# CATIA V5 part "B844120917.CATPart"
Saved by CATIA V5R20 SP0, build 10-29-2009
Part number: B844120917
Revision: 2
Definition: design
Nomenclature: B844120917
Source: made
Description: NOT SPECIFIED
Bounding box of the stored display mesh (mm): x -12.5 to 12.5, y -12.5 to 12.5, z -9 to 17
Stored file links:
  C:\Users\Utente\Desktop\3D files B844\B844120917.CATPart
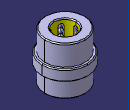
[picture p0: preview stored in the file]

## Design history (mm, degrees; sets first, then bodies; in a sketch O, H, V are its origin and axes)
Body1 "MANIFOLD_SOLID_BREP #38" (main body)
  Solid1: solid without history
Body2 "MANIFOLD_SOLID_BREP #76"
  Solid2: solid without history
Body3 "MANIFOLD_SOLID_BREP #114"
  Solid3: solid without history
Body4 "MANIFOLD_SOLID_BREP #152"
  Solid4: solid without history
Body5 "MANIFOLD_SOLID_BREP #190"
  Solid5: solid without history
Body6 "MANIFOLD_SOLID_BREP #228"
  Solid6: solid without history
Body7 "MANIFOLD_SOLID_BREP #266"
  Solid7: solid without history
Body8 "MANIFOLD_SOLID_BREP #1936"
  Solid8: solid without history
Body9 "MANIFOLD_SOLID_BREP #1974"
  Solid9: solid without history
Body10 "MANIFOLD_SOLID_BREP #2012"
  Solid10: solid without history
Body11 "MANIFOLD_SOLID_BREP #2050"
  Solid11: solid without history
Body12 "MANIFOLD_SOLID_BREP #2088"
  Solid12: solid without history
Body13 "MANIFOLD_SOLID_BREP #2126"
  Solid13: solid without history
Body14 "MANIFOLD_SOLID_BREP #2164"
  Solid14: solid without history
Body15 "MANIFOLD_SOLID_BREP #2202"
  Solid15: solid without history
Body16 "MANIFOLD_SOLID_BREP #2240"
  Solid16: solid without history
Body17 "MANIFOLD_SOLID_BREP #2278"
  Solid17: solid without history
Body18 "MANIFOLD_SOLID_BREP #2316"
  Solid18: solid without history
Body19 "MANIFOLD_SOLID_BREP #2354"
  Solid19: solid without history
Body20 "MANIFOLD_SOLID_BREP #2392"
  Solid20: solid without history
Body21 "MANIFOLD_SOLID_BREP #2430"
  Solid21: solid without history
Body22 "MANIFOLD_SOLID_BREP #2468"
  Solid22: solid without history
Body23 "MANIFOLD_SOLID_BREP #2506"
  Solid23: solid without history
Body24 "MANIFOLD_SOLID_BREP #2544"
  Solid24: solid without history
Body25 "MANIFOLD_SOLID_BREP #2582"
  Solid25: solid without history
Body26 "MANIFOLD_SOLID_BREP #2620"
  Solid26: solid without history
Body27 "MANIFOLD_SOLID_BREP #2658"
  Solid27: solid without history
Body28 "MANIFOLD_SOLID_BREP #2696"
  Solid28: solid without history
Body29 "MANIFOLD_SOLID_BREP #2734"
  Solid29: solid without history
Body30 "MANIFOLD_SOLID_BREP #2772"
  Solid30: solid without history
Body31 "MANIFOLD_SOLID_BREP #2810"
  Solid31: solid without history
Body32 "MANIFOLD_SOLID_BREP #2848"
  Solid32: solid without history
Body33 "MANIFOLD_SOLID_BREP #2886"
  Solid33: solid without history
Body34 "MANIFOLD_SOLID_BREP #2924"
  Solid34: solid without history
Body35 "MANIFOLD_SOLID_BREP #2962"
  Solid35: solid without history
Body36 "MANIFOLD_SOLID_BREP #3000"
  Solid36: solid without history
Body37 "MANIFOLD_SOLID_BREP #3038"
  Solid37: solid without history
Body38 "MANIFOLD_SOLID_BREP #3076"
  Solid38: solid without history
Body39 "MANIFOLD_SOLID_BREP #3114"
  Solid39: solid without history
Body40 "MANIFOLD_SOLID_BREP #3152"
  Solid40: solid without history
Body41 "MANIFOLD_SOLID_BREP #3190"
  Solid41: solid without history
Body42 "MANIFOLD_SOLID_BREP #3228"
  Solid42: solid without history
Body43 "MANIFOLD_SOLID_BREP #3266"
  Solid43: solid without history
Body44 "MANIFOLD_SOLID_BREP #3304"
  Solid44: solid without history
Body45 "MANIFOLD_SOLID_BREP #3342"
  Solid45: solid without history
Body46 "MANIFOLD_SOLID_BREP #3380"
  Solid46: solid without history
Body47 "MANIFOLD_SOLID_BREP #3418"
  Solid47: solid without history
Body48 "MANIFOLD_SOLID_BREP #3456"
  Solid48: solid without history
Body49 "MANIFOLD_SOLID_BREP #3494"
  Solid49: solid without history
